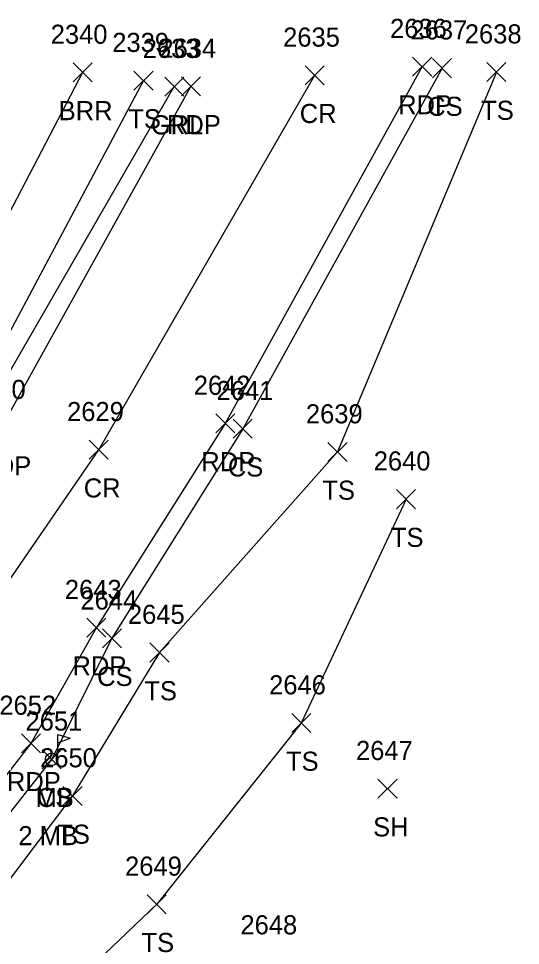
# Model space of a CAD drawing. Extents: x 1504228 to 1506103, y 437717 to 440106.
# Drawn here: x 1505420 to 1505472.6, y 438175.7 to 438272.8 of the extents above; entities that cross this region are included whole.
import ezdxf

# ---------------------------------------------------------------- set-up
doc = ezdxf.new("R2010")
doc.units = 0
for name, color, linetype in [('L_A', 7, 'Continuous'), ('L_C', 7, 'Continuous'), ('L_I', 7, 'Continuous'), ('L_TIC', 7, 'Continuous'), ('LABL', 7, 'Continuous'), ('LELB', 7, 'Continuous'), ('LMB', 7, 'Continuous'), ('P_A', 7, 'Continuous'), ('P_I', 7, 'Continuous'), ('P_TIC', 7, 'Continuous'), ('PET', 7, 'Continuous'), ('PRC', 7, 'Continuous'), ('R_A', 7, 'Continuous'), ('R_I', 7, 'Continuous'), ('R_TIC', 7, 'Continuous'), ('RGR', 7, 'Continuous')]:
    doc.layers.add(name, color=color, linetype=linetype)

msp = doc.modelspace()

# ---------------------------------------------------------------- linework, layer by layer
at = {"layer": 'L_TIC'}
for points in [[(1505425.709, 438266.128), (1505427.709, 438268.128)], [(1505427.709, 438266.128), (1505425.709, 438268.128)], [(1505463.371, 438266.578), (1505465.371, 438268.578)], [(1505465.371, 438266.578), (1505463.371, 438268.578)], [(1505469.06, 438266.163), (1505471.06, 438268.163)], [(1505471.06, 438266.163), (1505469.06, 438268.163)], [(1505432.081, 438265.273), (1505434.081, 438267.273)], [(1505434.081, 438265.273), (1505432.081, 438267.273)], [(1505442.482, 438228.816), (1505444.482, 438230.816)], [(1505444.482, 438228.816), (1505442.482, 438230.816)], [(1505452.418, 438226.384), (1505454.418, 438228.384)], [(1505454.418, 438226.384), (1505452.418, 438228.384)], [(1505459.601, 438221.447), (1505461.601, 438223.447)], [(1505461.601, 438221.447), (1505459.601, 438223.447)], [(1505428.783, 438206.884), (1505430.783, 438208.884)], [(1505430.783, 438206.884), (1505428.783, 438208.884)], [(1505433.759, 438205.384), (1505435.759, 438207.384)], [(1505435.759, 438205.384), (1505433.759, 438207.384)], [(1505448.611, 438198.006), (1505450.611, 438200.006)], [(1505450.611, 438198.006), (1505448.611, 438200.006)], [(1505422.465, 438194.212), (1505424.465, 438196.212)], [(1505424.465, 438194.212), (1505422.465, 438196.212)], [(1505457.657, 438191.13), (1505459.657, 438193.13)], [(1505459.657, 438191.13), (1505457.657, 438193.13)], [(1505424.646, 438190.367), (1505426.646, 438192.367)], [(1505426.646, 438190.367), (1505424.646, 438192.367)], [(1505433.468, 438179.022), (1505435.468, 438181.022)], [(1505435.468, 438179.022), (1505433.468, 438181.022)]]:
    msp.add_lwpolyline(points, dxfattribs=at)
at = {"layer": 'LABL'}
msp.add_lwpolyline([(1505426.709, 438267.128), (1505407.768, 438230.9), (1505394.085, 438210.643), (1505390.776, 438201.917), (1505383.002, 438197.122), (1505370.464, 438191.891), (1505357.673, 438183.248), (1505342.058, 438174.403)], dxfattribs=at)
at = {"layer": 'LELB'}
for points in [[(1505464.371, 438267.578), (1505443.482, 438229.816), (1505429.783, 438207.884), (1505423.465, 438195.212), (1505405.53, 438172.403), (1505390.919, 438151.584), (1505377.655, 438135.332), (1505367.909, 438121.411), (1505365.569, 438112.166), (1505365.649, 438106.069), (1505369.049, 438099.624), (1505384, 438089.64), (1505418.55, 438070.496), (1505425.632, 438075.745)], [(1505470.06, 438267.163), (1505453.418, 438227.384), (1505434.759, 438206.384), (1505425.646, 438191.367), (1505409.704, 438170.307), (1505396.192, 438148.093), (1505385.081, 438132.429), (1505376.016, 438117.564), (1505375.312, 438100.628), (1505390.313, 438095.558), (1505425.632, 438075.745), (1505441.164, 438097.453)], [(1505433.081, 438266.273), (1505413.735, 438229.989), (1505398.795, 438208.567), (1505392.864, 438200.506)], [(1505460.601, 438222.447), (1505449.611, 438199.006), (1505434.468, 438180.022), (1505419.613, 438165.841), (1505418.197, 438153.284), (1505427.495, 438135.49), (1505434.259, 438123.437), (1505428.641, 438123.377), (1505423.022, 438108.926), (1505410.924, 438095.162), (1505396.207, 438105.91), (1505383.907, 438120.47), (1505385.081, 438132.429)]]:
    msp.add_lwpolyline(points, dxfattribs=at)
at = {"layer": 'LMB'}
for p, q in [((1505424.115, 438197.812), (1505425.409, 438197.43)), ((1505424.121, 438195.22), (1505424.12, 438197.815)), ((1505424.12, 438196.913), (1505425.403, 438197.421)), ((1505423.465, 438195.212), (1505423.465, 438195.212))]:
    msp.add_line(p, q, dxfattribs=at)
msp.add_circle((1505423.465, 438195.212), 0.656, dxfattribs=at)
at = {"layer": 'P_TIC'}
for points in [[(1505461.284, 438266.741), (1505463.284, 438268.741)], [(1505463.284, 438266.741), (1505461.284, 438268.741)], [(1505450.025, 438265.829), (1505452.025, 438267.829)], [(1505452.025, 438265.829), (1505450.025, 438267.829)], [(1505437.053, 438264.664), (1505439.053, 438266.664)], [(1505439.053, 438264.664), (1505437.053, 438266.664)], [(1505440.657, 438229.374), (1505442.657, 438231.374)], [(1505442.657, 438229.374), (1505440.657, 438231.374)], [(1505427.391, 438226.62), (1505429.391, 438228.62)], [(1505429.391, 438226.62), (1505427.391, 438228.62)], [(1505427.151, 438207.99), (1505429.151, 438209.99)], [(1505429.151, 438207.99), (1505427.151, 438209.99)], [(1505420.287, 438195.87), (1505422.287, 438197.87)], [(1505422.287, 438195.87), (1505420.287, 438197.87)]]:
    msp.add_lwpolyline(points, dxfattribs=at)
at = {"layer": 'PET'}
for points in [[(1505462.284, 438267.741), (1505441.657, 438230.374), (1505428.151, 438208.99), (1505421.287, 438196.87), (1505403.557, 438174.106), (1505388.105, 438153.318), (1505374.877, 438136.75), (1505365.627, 438122.121), (1505363.383, 438112.135), (1505363.469, 438103.928), (1505366.164, 438099.366), (1505382.569, 438087.03)], [(1505311.676, 438134.175), (1505324.098, 438128.725), (1505335.82, 438133.23), (1505344.252, 438137.011), (1505351.761, 438143.58), (1505369.207, 438162.724), (1505390.677, 438190.218), (1505407.619, 438213.727), (1505418.189, 438229.936), (1505438.053, 438265.664)]]:
    msp.add_lwpolyline(points, dxfattribs=at)
at = {"layer": 'PRC'}
msp.add_lwpolyline([(1505338.301, 438109.134), (1505341.256, 438114.415), (1505356.739, 438132.535), (1505376.422, 438157.158), (1505399.585, 438185.376), (1505416.016, 438209.597), (1505428.391, 438227.62), (1505451.025, 438266.829)], dxfattribs=at)
at = {"layer": 'R_TIC'}
for points in [[(1505435.312, 438264.645), (1505437.312, 438266.645)], [(1505437.312, 438264.645), (1505435.312, 438266.645)]]:
    msp.add_lwpolyline(points, dxfattribs=at)
at = {"layer": 'RGR'}
msp.add_lwpolyline([(1505381.79, 438190.333), (1505384.268, 438190.42), (1505390.057, 438193.61), (1505404.907, 438213.977), (1505416.914, 438232.111), (1505436.312, 438265.645)], dxfattribs=at)

# ---------------------------------------------------------------- texts
at = {"layer": 'L_A'}
for s, p in [('BRR', (1505424.197, 438262.128)), ('CS', (1505462.812, 438262.578)), ('TS', (1505468.47, 438262.163)), ('TS', (1505431.49, 438261.273)), ('CS', (1505441.923, 438224.816)), ('TS', (1505451.827, 438222.384)), ('TS', (1505459.01, 438217.447)), ('CS', (1505428.224, 438202.884)), ('TS', (1505433.169, 438201.384)), ('TS', (1505448.02, 438194.006)), ('MB', (1505421.772, 438190.212)), ('CS', (1505421.906, 438190.212)), ('SH', (1505457.145, 438187.13)), ('TS', (1505424.056, 438186.367)), ('TS', (1505432.878, 438175.022))]:
    msp.add_text(s, height=2, dxfattribs=at).set_placement(p)
at = {"layer": 'L_C'}
msp.add_text('2 MB', height=2, dxfattribs=at).set_placement((1505419.977, 438186.212))
at = {"layer": 'L_I'}
for s, p in [('2637', (1505461.064, 438270.578)), ('2340', (1505423.362, 438270.128)), ('2638', (1505466.753, 438270.163)), ('2339', (1505429.813, 438269.273)), ('2641', (1505440.742, 438232.816)), ('2639', (1505450.103, 438230.384)), ('2640', (1505457.207, 438225.447)), ('2644', (1505426.476, 438210.884)), ('2645', (1505431.452, 438209.384)), ('2646', (1505446.249, 438202.006)), ('2651', (1505420.725, 438198.212)), ('2651', (1505420.725, 438198.212)), ('2647', (1505455.35, 438195.13)), ('2650', (1505422.253, 438194.367)), ('2649', (1505431.153, 438183.022)), ('2648', (1505443.242, 438176.877))]:
    msp.add_text(s, height=2, dxfattribs=at).set_placement(p)
at = {"layer": 'P_A'}
for s, p in [('RDP', (1505459.772, 438262.741)), ('CR', (1505449.458, 438261.829)), ('RDP', (1505435.541, 438260.664)), ('RDP', (1505439.145, 438225.374)), ('RDP', (1505415.677, 438224.936)), ('CR', (1505426.824, 438222.62)), ('RDP', (1505425.64, 438203.99)), ('RDP', (1505418.776, 438191.87))]:
    msp.add_text(s, height=2, dxfattribs=at).set_placement(p)
at = {"layer": 'P_I'}
for s, p in [('2636', (1505458.922, 438270.741)), ('2635', (1505447.718, 438269.829)), ('2634', (1505434.746, 438268.664)), ('2630', (1505414.795, 438232.936)), ('2642', (1505438.35, 438233.374)), ('2629', (1505425.076, 438230.62)), ('2643', (1505424.844, 438211.99)), ('2652', (1505417.98, 438199.87))]:
    msp.add_text(s, height=2, dxfattribs=at).set_placement(p)
at = {"layer": 'R_A'}
msp.add_text('GRL', height=2, dxfattribs=at).set_placement((1505433.856, 438260.645))
at = {"layer": 'R_I'}
msp.add_text('2633', height=2, dxfattribs=at).set_placement((1505433.005, 438268.645))

doc.saveas('drawing.dxf')
